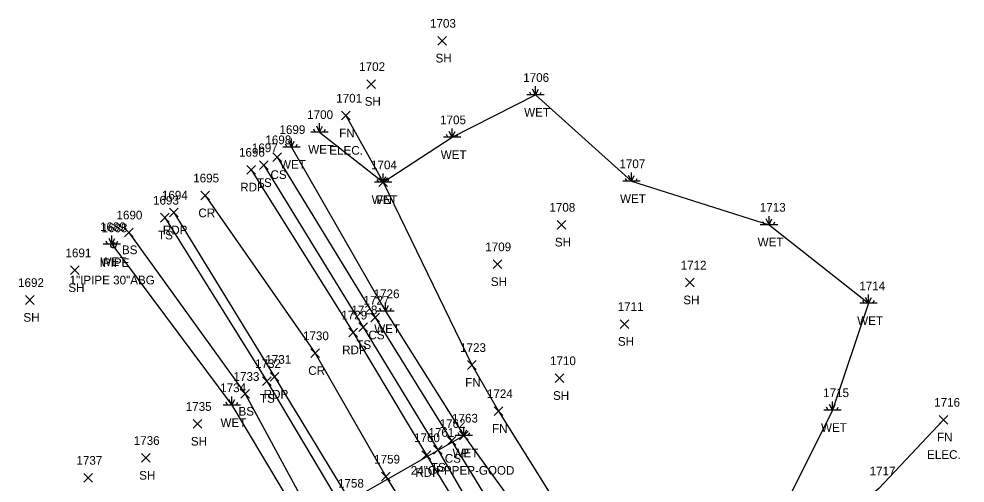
# Model space of a CAD drawing. Extents: x 1501299 to 1502485, y 381423 to 383765.
# Drawn here: x 1501299.2 to 1501516.8, y 383658 to 383764.8 of the extents above; entities that cross this region are included whole.
import ezdxf

# ---------------------------------------------------------------- set-up
doc = ezdxf.new("R2010")
doc.units = 0
for name, color, linetype in [('D_A', 7, 'Continuous'), ('D_C', 7, 'Continuous'), ('D_I', 7, 'Continuous'), ('D_TIC', 7, 'Continuous'), ('DCP', 7, 'Continuous'), ('L_A', 7, 'Continuous'), ('L_C', 7, 'Continuous'), ('L_I', 7, 'Continuous'), ('L_TIC', 7, 'Continuous'), ('LELB', 7, 'Continuous'), ('LFNC', 7, 'Continuous'), ('LWET', 7, 'Continuous'), ('M_A', 7, 'Continuous'), ('M_C', 7, 'Continuous'), ('M_I', 7, 'Continuous'), ('MPIP', 7, 'Continuous'), ('P_A', 7, 'Continuous'), ('P_I', 7, 'Continuous'), ('P_TIC', 7, 'Continuous'), ('PET', 7, 'Continuous'), ('PRC', 7, 'Continuous')]:
    doc.layers.add(name, color=color, linetype=linetype)

msp = doc.modelspace()

# ---------------------------------------------------------------- linework, layer by layer
at = {"layer": 'D_TIC'}
for points in [[(1501400.54, 383667.95), (1501402.54, 383669.95)], [(1501402.54, 383667.95), (1501400.54, 383669.95)]]:
    msp.add_lwpolyline(points, dxfattribs=at)
at = {"layer": 'DCP'}
msp.add_lwpolyline([(1501365.58, 383648.39), (1501401.54, 383668.95)], dxfattribs=at)
at = {"layer": 'L_TIC'}
for points in [[(1501395.51, 383758.77), (1501397.51, 383760.77)], [(1501397.51, 383758.77), (1501395.51, 383760.77)], [(1501379.23, 383748.82), (1501381.23, 383750.82)], [(1501381.23, 383748.82), (1501379.23, 383750.82)], [(1501373.37, 383741.56), (1501375.37, 383743.56)], [(1501375.37, 383741.56), (1501373.37, 383743.56)], [(1501357.62, 383731.98), (1501359.62, 383733.98)], [(1501359.62, 383731.98), (1501357.62, 383733.98)], [(1501354.51, 383730.14), (1501356.51, 383732.14)], [(1501356.51, 383730.14), (1501354.51, 383732.14)], [(1501381.94, 383726.21), (1501383.94, 383728.21)], [(1501383.94, 383726.21), (1501381.94, 383728.21)], [(1501331.79, 383718.08), (1501333.79, 383720.08)], [(1501333.79, 383718.08), (1501331.79, 383720.08)], [(1501422.96, 383716.45), (1501424.96, 383718.45)], [(1501424.96, 383716.45), (1501422.96, 383718.45)], [(1501323.47, 383714.68), (1501325.47, 383716.68)], [(1501325.47, 383714.68), (1501323.47, 383716.68)], [(1501408.22, 383707.36), (1501410.22, 383709.36)], [(1501410.22, 383707.36), (1501408.22, 383709.36)], [(1501311.1, 383705.97), (1501313.1, 383707.97)], [(1501313.1, 383705.97), (1501311.1, 383707.97)], [(1501452.48, 383703.15), (1501454.48, 383705.15)], [(1501454.48, 383703.15), (1501452.48, 383705.15)], [(1501300.75, 383699.14), (1501302.75, 383701.14)], [(1501302.75, 383699.14), (1501300.75, 383701.14)], [(1501380.14, 383695.09), (1501382.14, 383697.09)], [(1501382.14, 383695.09), (1501380.14, 383697.09)], [(1501377.37, 383692.86), (1501379.37, 383694.86)], [(1501379.37, 383692.86), (1501377.37, 383694.86)], [(1501437.44, 383693.61), (1501439.44, 383695.61)], [(1501439.44, 383693.61), (1501437.44, 383695.61)], [(1501402.34, 383684.19), (1501404.34, 383686.19)], [(1501404.34, 383684.19), (1501402.34, 383686.19)], [(1501422.53, 383681.16), (1501424.53, 383683.16)], [(1501424.53, 383681.16), (1501422.53, 383683.16)], [(1501355.21, 383680.5), (1501357.21, 383682.5)], [(1501357.21, 383680.5), (1501355.21, 383682.5)], [(1501350.26, 383677.54), (1501352.26, 383679.54)], [(1501352.26, 383677.54), (1501350.26, 383679.54)], [(1501408.51, 383673.58), (1501410.51, 383675.58)], [(1501410.51, 383673.58), (1501408.51, 383675.58)], [(1501339.26, 383670.64), (1501341.26, 383672.64)], [(1501341.26, 383670.64), (1501339.26, 383672.64)], [(1501510.83, 383671.59), (1501512.83, 383673.59)], [(1501512.83, 383671.59), (1501510.83, 383673.59)], [(1501397.69, 383666.71), (1501399.69, 383668.71)], [(1501399.69, 383666.71), (1501397.69, 383668.71)], [(1501394.55, 383664.66), (1501396.55, 383666.66)], [(1501396.55, 383664.66), (1501394.55, 383666.66)], [(1501327.37, 383662.81), (1501329.37, 383664.81)], [(1501329.37, 383662.81), (1501327.37, 383664.81)], [(1501314.13, 383658.25), (1501316.13, 383660.25)], [(1501316.13, 383658.25), (1501314.13, 383660.25)]]:
    msp.add_lwpolyline(points, dxfattribs=at)
at = {"layer": 'LELB'}
for points in [[(1501358.62, 383732.98), (1501381.14, 383696.09), (1501398.69, 383667.71), (1501415.46, 383640.29), (1501435.3, 383603.99), (1501464.9, 383561.23), (1501485.32, 383525.1), (1501505.06, 383497.04), (1501522.93, 383468.15), (1501546.42, 383435.55), (1501564.6, 383407.15), (1501589.27, 383369.8), (1501600.38, 383363.76)], [(1501355.51, 383731.14), (1501378.37, 383693.86), (1501395.55, 383665.66), (1501411.45, 383638.21), (1501433.32, 383602.63), (1501461.34, 383558.64), (1501483.16, 383524.05), (1501502.07, 383494.51), (1501520.43, 383466.23), (1501542.02, 383433.96), (1501561.69, 383405.4), (1501588.28, 383366.16), (1501592.45, 383361.85)], [(1501332.79, 383719.08), (1501356.21, 383681.5), (1501373.29, 383652.69), (1501388.57, 383624.23), (1501410.59, 383588.65), (1501439.07, 383543.46), (1501460.07, 383509.46), (1501480.49, 383480.19), (1501499.63, 383452.74), (1501519.17, 383422.52), (1501533.38, 383399.88)], [(1501324.47, 383715.68), (1501351.26, 383678.54), (1501366.23, 383650.78), (1501368.72, 383645.59), (1501384.78, 383621.73), (1501405.54, 383585.19), (1501432.56, 383539.71)]]:
    msp.add_lwpolyline(points, dxfattribs=at)
at = {"layer": 'LFNC'}
for points in [[(1501374.37, 383742.56), (1501382.94, 383727.21), (1501403.34, 383685.19), (1501409.51, 383674.58), (1501426.09, 383647.98), (1501436.22, 383631.2), (1501450.55, 383610.14), (1501477.09, 383568.96), (1501495.83, 383538.88), (1501500.46, 383533.1), (1501519.53, 383507.11), (1501541.76, 383477.61), (1501544.05, 383474.54), (1501551.42, 383461.96)], [(1501511.83, 383672.59), (1501496.93, 383656.8), (1501474.52, 383638.72), (1501455.81, 383630.44), (1501436.22, 383631.2)]]:
    msp.add_lwpolyline(points, dxfattribs=at)
at = {"layer": 'LWET'}
for p, q in [((1501417, 383747.31), (1501416.66, 383747.97)), ((1501418, 383747.31), (1501417.33, 383748.64)), ((1501418, 383747.31), (1501418, 383749.31)), ((1501418, 383747.31), (1501418.66, 383748.64)), ((1501419, 383747.31), (1501419.33, 383747.97)), ((1501420, 383747.31), (1501416, 383747.31)), ((1501367.35, 383738.78), (1501367.02, 383739.45)), ((1501368.35, 383738.78), (1501367.68, 383740.12)), ((1501368.35, 383738.78), (1501368.35, 383740.78)), ((1501368.35, 383738.78), (1501369.02, 383740.12)), ((1501369.35, 383738.78), (1501369.68, 383739.45)), ((1501398.82, 383737.57), (1501398.82, 383739.57)), ((1501361.86, 383735.32), (1501361.86, 383737.32)), ((1501370.35, 383738.78), (1501366.35, 383738.78)), ((1501400.82, 383737.57), (1501396.82, 383737.57)), ((1501397.82, 383737.57), (1501397.49, 383738.24)), ((1501398.82, 383737.57), (1501398.15, 383738.91)), ((1501398.82, 383737.57), (1501399.49, 383738.91)), ((1501399.82, 383737.57), (1501400.15, 383738.24)), ((1501363.86, 383735.32), (1501359.86, 383735.32)), ((1501360.86, 383735.32), (1501360.53, 383735.98)), ((1501361.86, 383735.32), (1501361.2, 383736.65)), ((1501361.86, 383735.32), (1501362.53, 383736.65)), ((1501362.86, 383735.32), (1501363.2, 383735.98)), ((1501382.94, 383727.21), (1501382.28, 383728.55)), ((1501382.94, 383727.21), (1501382.94, 383729.21)), ((1501382.94, 383727.21), (1501383.61, 383728.55)), ((1501440.05, 383727.46), (1501439.38, 383728.79)), ((1501440.05, 383727.46), (1501440.05, 383729.46)), ((1501440.05, 383727.46), (1501440.71, 383728.79)), ((1501384.94, 383727.21), (1501380.94, 383727.21)), ((1501381.94, 383727.21), (1501381.61, 383727.88)), ((1501383.94, 383727.21), (1501384.28, 383727.88)), ((1501442.05, 383727.46), (1501438.05, 383727.46)), ((1501439.05, 383727.46), (1501438.71, 383728.12)), ((1501441.05, 383727.46), (1501441.38, 383728.12)), ((1501470.68, 383717.46), (1501470.35, 383718.12)), ((1501471.68, 383717.46), (1501471.02, 383718.79)), ((1501471.68, 383717.46), (1501471.68, 383719.46)), ((1501471.68, 383717.46), (1501472.35, 383718.79)), ((1501472.68, 383717.46), (1501473.02, 383718.12)), ((1501473.68, 383717.46), (1501469.68, 383717.46)), ((1501319.6, 383712.99), (1501319.27, 383713.66)), ((1501320.6, 383712.99), (1501319.94, 383714.32)), ((1501320.6, 383712.99), (1501320.6, 383714.99)), ((1501320.6, 383712.99), (1501321.27, 383714.32)), ((1501321.6, 383712.99), (1501321.94, 383713.66)), ((1501322.6, 383712.99), (1501318.6, 383712.99)), ((1501494.57, 383699.38), (1501493.9, 383700.71)), ((1501494.57, 383699.38), (1501494.57, 383701.38)), ((1501494.57, 383699.38), (1501495.24, 383700.71)), ((1501382.52, 383697.56), (1501382.19, 383698.23)), ((1501383.52, 383697.56), (1501382.85, 383698.89)), ((1501383.52, 383697.56), (1501383.52, 383699.56)), ((1501383.52, 383697.56), (1501384.19, 383698.89)), ((1501384.52, 383697.56), (1501384.85, 383698.23)), ((1501496.57, 383699.38), (1501492.57, 383699.38)), ((1501493.57, 383699.38), (1501493.24, 383700.04)), ((1501495.57, 383699.38), (1501495.9, 383700.04)), ((1501385.52, 383697.56), (1501381.52, 383697.56)), ((1501347.18, 383675.94), (1501346.84, 383676.6)), ((1501348.18, 383675.94), (1501347.51, 383677.27)), ((1501348.18, 383675.94), (1501348.18, 383677.94)), ((1501348.18, 383675.94), (1501348.84, 383677.27)), ((1501349.18, 383675.94), (1501349.51, 383676.6)), ((1501486.25, 383674.8), (1501486.25, 383676.8)), ((1501350.18, 383675.94), (1501346.18, 383675.94)), ((1501488.25, 383674.8), (1501484.25, 383674.8)), ((1501485.25, 383674.8), (1501484.92, 383675.47)), ((1501486.25, 383674.8), (1501485.59, 383676.13)), ((1501486.25, 383674.8), (1501486.92, 383676.13)), ((1501487.25, 383674.8), (1501487.59, 383675.47)), ((1501401.54, 383668.95), (1501400.88, 383670.29)), ((1501401.54, 383668.95), (1501401.54, 383670.95)), ((1501401.54, 383668.95), (1501402.21, 383670.29)), ((1501403.54, 383668.95), (1501399.54, 383668.95)), ((1501400.54, 383668.95), (1501400.21, 383669.62)), ((1501402.54, 383668.95), (1501402.88, 383669.62))]:
    msp.add_line(p, q, dxfattribs=at)
for points in [[(1501368.35, 383738.78), (1501382.94, 383727.21), (1501398.82, 383737.57), (1501418, 383747.31), (1501440.05, 383727.46), (1501471.68, 383717.46), (1501494.57, 383699.38), (1501486.25, 383674.8), (1501474.27, 383650.63), (1501460.73, 383643.27), (1501445.76, 383639.75), (1501426.09, 383647.98), (1501433.24, 383627.92), (1501444.4, 383608.06), (1501471.74, 383565.71), (1501493.36, 383531.32), (1501500.46, 383533.1), (1501510.21, 383549.97), (1501525.64, 383560.99), (1501540.9, 383568.85), (1501552.66, 383578.59)], [(1501361.86, 383735.32), (1501383.52, 383697.56), (1501401.54, 383668.95), (1501420.14, 383643.24), (1501429.42, 383625.36), (1501440.42, 383606.65), (1501468.13, 383563.3), (1501489.26, 383528.35), (1501508.23, 383499.7), (1501528.29, 383471.48), (1501550.47, 383437.33), (1501555.06, 383441.42)], [(1501320.6, 383712.99), (1501348.18, 383675.94), (1501362.98, 383651.17), (1501365.24, 383648.78)]]:
    msp.add_lwpolyline(points, dxfattribs=at)
at = {"layer": 'MPIP'}
for radius in [0.625, 0.0833]:
    msp.add_circle((1501320.94, 383712.73), radius, dxfattribs=at)
at = {"layer": 'P_TIC'}
for points in [[(1501351.61, 383729.1), (1501353.61, 383731.1)], [(1501353.61, 383729.1), (1501351.61, 383731.1)], [(1501341.03, 383723.18), (1501343.03, 383725.18)], [(1501343.03, 383723.18), (1501341.03, 383725.18)], [(1501333.83, 383719.25), (1501335.83, 383721.25)], [(1501335.83, 383719.25), (1501333.83, 383721.25)], [(1501375.04, 383691.66), (1501377.04, 383693.66)], [(1501377.04, 383691.66), (1501375.04, 383693.66)], [(1501366.31, 383686.9), (1501368.31, 383688.9)], [(1501368.31, 383686.9), (1501366.31, 383688.9)], [(1501357.01, 383681.47), (1501359.01, 383683.47)], [(1501359.01, 383681.47), (1501357.01, 383683.47)], [(1501391.89, 383663.45), (1501393.89, 383665.45)], [(1501393.89, 383663.45), (1501391.89, 383665.45)], [(1501382.59, 383658.52), (1501384.59, 383660.52)], [(1501384.59, 383658.52), (1501382.59, 383660.52)]]:
    msp.add_lwpolyline(points, dxfattribs=at)
at = {"layer": 'PET'}
for points in [[(1501352.61, 383730.1), (1501376.04, 383692.66), (1501392.89, 383664.45), (1501409.55, 383637.05), (1501431.22, 383601.01), (1501459.29, 383556.77), (1501480.73, 383522.39), (1501500.04, 383493.11), (1501518.67, 383465.09), (1501539.81, 383433.29), (1501559.66, 383403.85), (1501585.89, 383364.55), (1501607.04, 383333.42), (1501616.49, 383318.82), (1501608.79, 383312.41), (1501601.65, 383306.28)], [(1501334.83, 383720.25), (1501358.01, 383682.47), (1501375.27, 383653.98), (1501391.81, 383626.28), (1501413.67, 383590.16), (1501441.93, 383545.3), (1501463.31, 383511.64), (1501483.05, 383481.71), (1501501.39, 383453.56), (1501521.79, 383422.95), (1501532.7, 383406.6), (1501560.32, 383365.3), (1501580.55, 383335.85), (1501587.21, 383326.16), (1501601.65, 383306.28)]]:
    msp.add_lwpolyline(points, dxfattribs=at)
at = {"layer": 'PRC'}
msp.add_lwpolyline([(1501342.03, 383724.18), (1501367.31, 383687.9), (1501383.59, 383659.52), (1501401.02, 383631.48), (1501422.76, 383595.53), (1501451.02, 383550.58), (1501471.94, 383517.22), (1501491.45, 383487.69), (1501510.59, 383459), (1501530.12, 383428.74), (1501550.99, 383398.39), (1501579.41, 383355.49), (1501608.79, 383312.41)], dxfattribs=at)

# ---------------------------------------------------------------- texts
at = {"layer": 'D_A'}
msp.add_text('P', height=2, dxfattribs=at).set_placement((1501400.92, 383663.95))
at = {"layer": 'D_C'}
msp.add_text('24"CPPPEP-GOOD', height=2, dxfattribs=at).set_placement((1501389.3, 383659.95))
at = {"layer": 'D_I'}
msp.add_text('1763', height=2, dxfattribs=at).set_placement((1501398.8, 383671.95))
at = {"layer": 'L_A'}
for s, p in [('SH', (1501395, 383754.77)), ('SH', (1501378.71, 383744.82)), ('WET', (1501415.38, 383742.31)), ('FN', (1501372.85, 383737.56)), ('WET', (1501365.73, 383733.78)), ('WET', (1501396.2, 383732.57)), ('WET', (1501359.24, 383730.32)), ('CS', (1501357.06, 383727.98)), ('TS', (1501353.92, 383726.14)), ('WET', (1501380.32, 383722.21)), ('FN', (1501381.42, 383722.21)), ('WET', (1501437.43, 383722.46)), ('TS', (1501331.2, 383714.08)), ('SH', (1501422.45, 383712.45)), ('WET', (1501469.06, 383712.46)), ('BS', (1501322.91, 383710.68)), ('WET', (1501317.98, 383707.99)), ('SH', (1501407.71, 383703.36)), ('SH', (1501310.58, 383701.97)), ('SH', (1501451.97, 383699.15)), ('SH', (1501300.24, 383695.14)), ('WET', (1501491.95, 383694.38)), ('WET', (1501380.9, 383692.56)), ('CS', (1501379.58, 383691.09)), ('SH', (1501436.93, 383689.61)), ('TS', (1501376.78, 383688.86)), ('FN', (1501401.82, 383680.19)), ('TS', (1501354.62, 383676.5)), ('SH', (1501422.02, 383677.16)), ('BS', (1501349.7, 383673.54)), ('WET', (1501345.56, 383670.94)), ('WET', (1501483.63, 383669.8)), ('FN', (1501407.99, 383669.58)), ('SH', (1501338.75, 383666.64)), ('FN', (1501510.31, 383667.59)), ('WET', (1501398.92, 383663.95)), ('CS', (1501397.13, 383662.71)), ('TS', (1501393.96, 383660.66)), ('SH', (1501326.86, 383658.81))]:
    msp.add_text(s, height=2, dxfattribs=at).set_placement(p)
at = {"layer": 'L_C'}
for p in [(1501370.58, 383733.56), (1501508.03, 383663.59)]:
    msp.add_text('ELEC.', height=2, dxfattribs=at).set_placement(p)
at = {"layer": 'L_I'}
for s, p in [('1703', (1501393.74, 383762.77)), ('1702', (1501377.45, 383752.82)), ('1706', (1501415.17, 383750.31)), ('1701', (1501372.17, 383745.56)), ('1700', (1501365.49, 383741.78)), ('1705', (1501396.05, 383740.57)), ('1699', (1501359.12, 383738.32)), ('1698', (1501355.88, 383735.98)), ('1697', (1501352.77, 383734.14)), ('1704', (1501380.17, 383730.21)), ('1704', (1501380.17, 383730.21)), ('1707', (1501437.28, 383730.46)), ('1693', (1501330.05, 383722.08)), ('1708', (1501421.19, 383720.45)), ('1713', (1501469.56, 383720.46)), ('1690', (1501321.65, 383718.68)), ('1689', (1501317.85, 383715.99)), ('1709', (1501406.44, 383711.36)), ('1691', (1501309.92, 383709.97)), ('1712', (1501451.36, 383707.15)), ('1692', (1501299.01, 383703.14)), ('1726', (1501380.77, 383700.56)), ('1714', (1501492.44, 383702.38)), ('1727', (1501378.45, 383699.09)), ('1728', (1501375.68, 383696.86)), ('1711', (1501436.88, 383697.61)), ('1723', (1501400.65, 383688.19)), ('1710', (1501421.32, 383685.16)), ('1732', (1501353.52, 383684.5)), ('1733', (1501348.56, 383681.54)), ('1734', (1501345.49, 383678.94)), ('1724', (1501406.82, 383677.58)), ('1715', (1501484.13, 383677.8)), ('1735', (1501337.57, 383674.64)), ('1716', (1501509.65, 383675.59)), ('1763', (1501398.8, 383671.95)), ('1762', (1501395.95, 383670.71)), ('1761', (1501393.38, 383668.66)), ('1736', (1501325.62, 383666.81)), ('1737', (1501312.44, 383662.25)), ('1717', (1501494.81, 383659.8))]:
    msp.add_text(s, height=2, dxfattribs=at).set_placement(p)
at = {"layer": 'M_A'}
msp.add_text('IPIPE', height=2, dxfattribs=at).set_placement((1501317.77, 383707.73))
at = {"layer": 'M_C'}
msp.add_text('1"IPIPE 30"ABG', height=2, dxfattribs=at).set_placement((1501310.86, 383703.73))
at = {"layer": 'M_I'}
msp.add_text('1688', height=2, dxfattribs=at).set_placement((1501318.2, 383715.73))
at = {"layer": 'P_A'}
for s, p in [('RDP', (1501350.1, 383725.1)), ('CR', (1501340.47, 383719.18)), ('RDP', (1501332.31, 383715.25)), ('RDP', (1501373.53, 383687.66)), ('CR', (1501365.75, 383682.9)), ('RDP', (1501355.49, 383677.47)), ('RDP', (1501390.37, 383659.45))]:
    msp.add_text(s, height=2, dxfattribs=at).set_placement(p)
at = {"layer": 'P_I'}
for s, p in [('1696', (1501349.81, 383733.1)), ('1695', (1501339.29, 383727.18)), ('1694', (1501332.09, 383723.25)), ('1729', (1501373.34, 383695.66)), ('1730', (1501364.53, 383690.9)), ('1731', (1501355.88, 383685.47)), ('1760', (1501390.06, 383667.45)), ('1759', (1501380.89, 383662.52)), ('1758', (1501372.58, 383656.98))]:
    msp.add_text(s, height=2, dxfattribs=at).set_placement(p)

doc.saveas('drawing.dxf')
